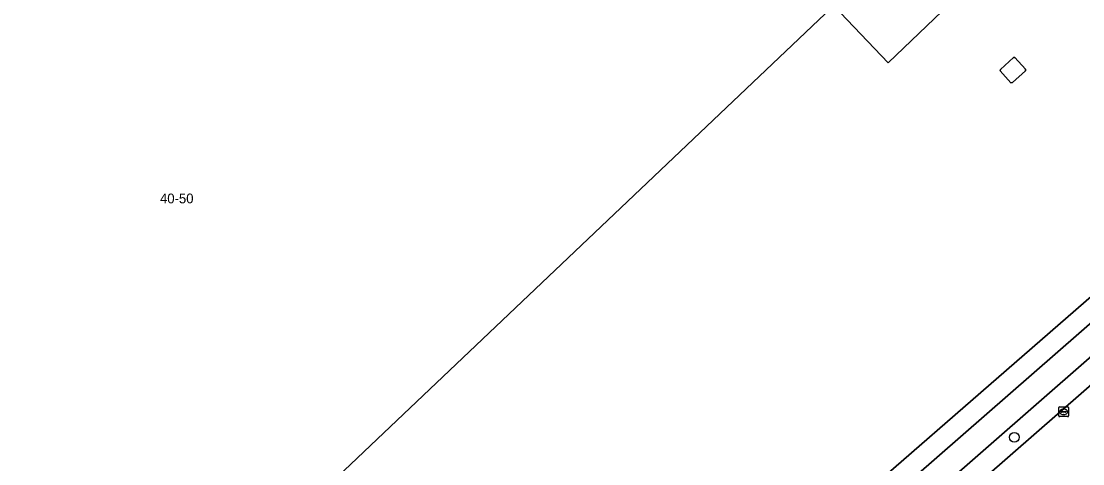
# Model space of a CAD drawing. Extents: x 156141 to 158132, y 385651 to 388333.
# Drawn here: x 156702 to 156810.3, y 387126.9 to 387172.1 of the extents above; entities that cross this region are included whole.
import ezdxf

# ---------------------------------------------------------------- set-up
doc = ezdxf.new("R2010")
doc.units = 0
for name, color, linetype in [('IMGEO_Berm_groen', 7, 'Continuous'), ('IMGEO_Boom', 7, 'Continuous'), ('IMGEO_Erf', 7, 'Continuous'), ('IMGEO_Fietspad_gesloten', 7, 'Continuous'), ('IMGEO_Groenvoorziening', 7, 'Continuous'), ('IMGEO_Hek', 7, 'Continuous'), ('IMGEO_Kolk', 7, 'Continuous'), ('IMGEO_Lage_trafo', 7, 'Continuous'), ('IMGEO_Pand', 7, 'Continuous'), ('IMGEO_Pand_nummerreeks', 7, 'Continuous'), ('IMGEO_Rijbaan_lokaal_gesloten', 7, 'Continuous')]:
    doc.layers.add(name, color=color, linetype=linetype)

msp = doc.modelspace()

# ---------------------------------------------------------------- linework, layer by layer
at = {"layer": 'IMGEO_Berm_groen'}
for points in [[(156852.34, 387173.89), (156759.08, 387092.27), (156729.58, 387066.45)], [(156721.13, 387056.5), (156720.95, 387056.76), (156727.81, 387062.18), (156731.09, 387064.97), (156760.5, 387090.68), (156852.84, 387171.4)]]:
    msp.add_lwpolyline(points, dxfattribs=at)
at = {"layer": 'IMGEO_Boom'}
msp.add_circle((156803.34, 387129.61), 0.489, dxfattribs=at)
at = {"layer": 'IMGEO_Erf'}
for points in [[(156847.3, 387233.05), (156806.29, 387194.08), (156806.14, 387193.94), (156800.61, 387188.71), (156800.48, 387188.58), (156797.25, 387185.52), (156797.09, 387185.36), (156799.95, 387182.37), (156799.32, 387181.78), (156801.2, 387179.78), (156795.94, 387174.77), (156796.76, 387173.9), (156790.45, 387167.87), (156784.89, 387173.71), (156784.71, 387173.53), (156719.46, 387111.52), (156719.3, 387111.36), (156718.51, 387110.61), (156699.41, 387092.47)], [(156701.8, 387051.67), (156704.11, 387052.67), (156706.16, 387053.58), (156708.33, 387054.92), (156710.4, 387056.28), (156712.25, 387057.77), (156755.91, 387095.83), (156856.27, 387183.3)]]:
    msp.add_lwpolyline(points, dxfattribs=at)
msp.add_lwpolyline([(156804.48, 387167.22), (156804.48, 387167.04), (156803.14, 387165.84), (156802.99, 387165.83), (156801.89, 387167.04), (156801.93, 387167.19), (156803.24, 387168.42), (156803.4, 387168.41)], close=True, dxfattribs=at)
at = {"layer": 'IMGEO_Fietspad_gesloten'}
for points in [[(156850.7, 387175.91), (156757.33, 387094.23), (156727.84, 387068.43)], [(156729.58, 387066.45), (156759.08, 387092.27), (156852.34, 387173.89)]]:
    msp.add_lwpolyline(points, dxfattribs=at)
at = {"layer": 'IMGEO_Groenvoorziening'}
for points in [[(156856.27, 387183.3), (156755.91, 387095.83), (156712.25, 387057.77), (156710.4, 387056.28), (156708.33, 387054.92), (156706.16, 387053.58), (156704.11, 387052.67), (156701.8, 387051.67), (156699.58, 387050.72), (156697.33, 387049.72), (156694.93, 387049.27), (156692.53, 387048.75), (156690.17, 387048.6), (156687.72, 387048.8), (156685.31, 387049.37), (156683.11, 387050.12), (156681.07, 387051.51), (156679.47, 387053.51), (156651.79, 387085.45)], [(156727.84, 387068.43), (156757.33, 387094.23), (156850.7, 387175.91)]]:
    msp.add_lwpolyline(points, dxfattribs=at)
at = {"layer": 'IMGEO_Hek'}
msp.add_lwpolyline([(156755.91, 387095.83), (156856.27, 387183.3)], dxfattribs=at)
at = {"layer": 'IMGEO_Kolk'}
for p, q in [((156807.87, 387131.79), (156807.87, 387132.64)), ((156807.95, 387132.72), (156808.8, 387132.72)), ((156808.13, 387132.21), (156808.13, 387132.22)), ((156808.17, 387132.26), (156808.57, 387132.26)), ((156808.57, 387132.17), (156808.17, 387132.17)), ((156808.36, 387132.5), (156808.39, 387132.5)), ((156808.38, 387131.94), (156808.36, 387131.94)), ((156808.62, 387132.22), (156808.62, 387132.21)), ((156808.87, 387132.64), (156808.87, 387131.79)), ((156808.8, 387131.72), (156807.95, 387131.72))]:
    msp.add_line(p, q, dxfattribs=at)
for points in [[(156807.87, 387131.79), (156807.87, 387132.64)], [(156807.95, 387132.72), (156808.8, 387132.72)], [(156808.87, 387132.64), (156808.87, 387131.79)], [(156808.8, 387131.72), (156807.95, 387131.72)]]:
    msp.add_lwpolyline(points, dxfattribs=at)
for centre, radius, start, end in [((156807.95, 387132.64), 0.0765, 91.552, 178.448), ((156807.95, 387132.64), 0.0765, 91.552, 178.448), ((156807.95, 387131.79), 0.0765, 181.552, 268.448), ((156807.95, 387131.79), 0.0765, 181.552, 268.448), ((156808.17, 387132.22), 0.0403, 85.8775, 175.7526), ((156808.17, 387132.21), 0.0366, 178.938, 274.7102), ((156808.58, 387132.22), 0.0386, 1.7309, 96.639), ((156808.57, 387132.22), 0.043, 264.8664, 352.4533), ((156808.8, 387132.64), 0.0765, 1.552, 88.448), ((156808.8, 387132.64), 0.0765, 1.552, 88.448), ((156808.8, 387131.79), 0.0765, 271.552, 358.448), ((156808.8, 387131.79), 0.0765, 271.552, 358.448)]:
    msp.add_arc(centre, radius, start, end, dxfattribs=at)
for centre, major_axis, ratio, start_param, end_param in [((156808.36, 387132.22), (-0.387, 0.002), 0.722429, 4.712389, 7.853982), ((156808.38, 387132.22), (-0.39, 0.002), 0.717154, 1.570796, 4.712389)]:
    msp.add_ellipse(centre, major_axis=major_axis, ratio=ratio, start_param=start_param, end_param=end_param, dxfattribs=at)
at = {"layer": 'IMGEO_Lage_trafo'}
msp.add_lwpolyline([(156802.99, 387165.83), (156803.14, 387165.84), (156804.48, 387167.04), (156804.48, 387167.22), (156803.4, 387168.41), (156803.24, 387168.42), (156801.93, 387167.19), (156801.89, 387167.04)], close=True, dxfattribs=at)
at = {"layer": 'IMGEO_Pand'}
msp.add_lwpolyline([(156699.41, 387092.47), (156718.51, 387110.61), (156719.3, 387111.36), (156719.46, 387111.52), (156784.71, 387173.53), (156784.89, 387173.71), (156790.45, 387167.87), (156796.76, 387173.9), (156795.94, 387174.77), (156801.2, 387179.78), (156799.32, 387181.78), (156799.95, 387182.37), (156797.09, 387185.36), (156797.25, 387185.52), (156800.48, 387188.58), (156800.61, 387188.71), (156806.14, 387193.94), (156806.29, 387194.08), (156847.3, 387233.05)], dxfattribs=at)
at = {"layer": 'IMGEO_Rijbaan_lokaal_gesloten'}
msp.add_lwpolyline([(156852.84, 387171.4), (156760.5, 387090.68), (156731.09, 387064.97), (156727.81, 387062.18), (156720.95, 387056.76), (156721.13, 387056.5)], dxfattribs=at)

# ---------------------------------------------------------------- texts
at = {"layer": 'IMGEO_Pand_nummerreeks'}
msp.add_text('40-50', height=1, dxfattribs=at).set_placement((156716.16, 387153.51))

doc.saveas('drawing.dxf')
